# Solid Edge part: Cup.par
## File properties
Title: Cup
Author: DESYS
Template: Normal.par
Last saved by: Luca
Revision: 10
Application: Solid Edge
Tipo di contenuto documento: 0
Precisione: 0,990
Document Number: 8044
Revision: 0
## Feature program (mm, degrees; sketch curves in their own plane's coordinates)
lofted protrusion "unnamed LoftedProtrusion 1"
lofted cutout "unnamed LoftedCutout 1"
sketch for "unnamed Protrusion 1" plane through (0, 0, -90) normal (0, 0, -1) x-axis (1, 0, 0)
  circle centre (0, 0) radius 85
extrude "unnamed Protrusion 1" add finite 20 along +normal
sketch for "Foro_1" plane through (0, 0, -110) normal (0, 0, -1) x-axis (1, 0, 0)
  hole centre (0, 0) bore radius 25
hole "Foro_1" diameter 50 through
sketch for "Foro_2" plane through (0, 0, -110) normal (0, 0, -1) x-axis (0, 1, 0)
  hole centre (0, -70) bore radius 6
hole "Foro_2" diameter 12 finite
sketch for "unnamed Hole 1" plane through (0, 0, -110) normal (0, 0, -1) x-axis (0, 1, 0)
  hole centre (0, 70) bore radius 6
hole "unnamed Hole 1" finite
sketch for "Foro_4" plane through (0, 0, -110) normal (0, 0, -1) x-axis (0, 1, 0)
  hole centre (-70, 0) bore radius 6
hole "Foro_4" diameter 12 finite
sketch for "unnamed Hole 2" plane through (0, 0, -110) normal (0, 0, -1) x-axis (0, 1, 0)
  hole centre (70, 0) bore radius 6
hole "unnamed Hole 2" finite
sketch for "ExtrudedCutout_1" #1 plane through (0, 0, -110) normal (0, 0, -1) x-axis (0, 1, 0)
  circle centre (0, 0) radius 37.5
sketch for "ExtrudedCutout_1" #2 plane through (0, 0, -110) normal (0, 0, -1) x-axis (0, 1, 0)
  arc centre (-53.4571, -12.9358) radius 10 from (-61.3347, -6.7759) to (-63.1766, -15.2877) ccw
  arc centre (0, 0) radius 65 from (-15.2877, -63.1766) to (-63.1766, -15.2877) cw
  arc centre (-12.9358, -53.4571) radius 10 from (-15.2877, -63.1766) to (-6.7759, -61.3347) ccw
  arc centre (12.9358, -53.4571) radius 10 from (6.7759, -61.3347) to (15.2877, -63.1766) ccw
  arc centre (0, 0) radius 65 from (63.1766, -15.2877) to (15.2877, -63.1766) cw
  arc centre (53.4571, -12.9358) radius 10 from (63.1766, -15.2877) to (61.3347, -6.7759) ccw
  arc centre (53.4571, 12.9358) radius 10 from (61.3347, 6.7759) to (63.1766, 15.2877) ccw
  arc centre (12.9358, 53.4571) radius 10 from (15.2877, 63.1766) to (6.7759, 61.3347) ccw
  arc centre (-12.9358, 53.4571) radius 10 from (-6.7759, 61.3347) to (-15.2877, 63.1766) ccw
  arc centre (0, 0) radius 65 from (-63.1766, 15.2877) to (-15.2877, 63.1766) cw
  arc centre (-53.4571, 12.9358) radius 10 from (-63.1766, 15.2877) to (-61.3347, 6.7759) ccw
extrude "ExtrudedCutout_1" cut finite 15 along -normal
sketch for "Foro_6" plane through (0, 0, -110) normal (0, 0, -1) x-axis (0, 1, 0)
  hole centre (-70, 0) bore radius 11
hole "Foro_6" diameter 22 finite
sketch for "unnamed Hole 3" plane through (0, 0, -110) normal (0, 0, -1) x-axis (0, 1, 0)
  hole centre (70, 0) bore radius 11
hole "unnamed Hole 3" finite
pattern "unnamed Pattern 1" of "Foro_6", "unnamed Hole 3"
fillet "Rotondo_1" radius 10
fillet "Rotondo_2" radius 7
fillet "Rotondo_3" radius 7
fillet "Rotondo_5" radius 5
fillet "Rotondo_7" radius 7
fillet "Rotondo_8" radius 6
fillet "Rotondo_9" radius 10
pattern "unnamed Pattern 2" of "Foro_2", "unnamed Hole 1"
pattern "unnamed Pattern 3" of "Foro_4", "unnamed Hole 2"
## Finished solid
Body 1: solid body, 78 faces, 157 edges, 80 vertices.
  Faces by surface: torus 37, cylinder 25, plane 11, blend 4, spline 1
  Edges by curve: circle 127, line 16, intersection 14
Bounding box of the edges (mm; curved faces can reach further): 448.553 x 448.553 x 110.000, from (-224.2767, -224.2767, -110) to (224.2767, 224.2767, 0).
Cylindrical faces by radius (mm): R6 x4, R10 x8, R11 x6, R25 x1, R37.5 x1, R65 x4, R85 x1
Toroidal faces (ring radius, tube radius in mm): R3 r7 x8, R6 r5 x2, R15 r5 x8, R18 r7 x4, R32.5 r5 x1, R44.5 r7 x1, R58 r7 x4, R70 r5 x4, R73.9188 r180 x1, R80 r5 x2, R95 r10 x1, R219.2647 r6 x1
Planar faces by outward normal: +z 1, -z 10
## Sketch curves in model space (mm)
arc centre (-36.2383, 0, 144.7253) radius 230 from (-214.9968, 0, 0) through (-130.1638, 0, -65.2223) to (-25, 0, -85)
circle centre (0, 0, -85) radius 25
circle centre (0, 0, -85) radius 25
circle centre (0, 0, 0) radius 215
arc centre (-73.9188, 0, 89.6586) radius 180 from (-230, 0, 0) through (-168.8441, 0, -63.2766) to (-85, 0, -90)
circle centre (0, 0, -90) radius 85
circle centre (0, 0, 0) radius 230
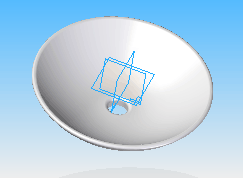
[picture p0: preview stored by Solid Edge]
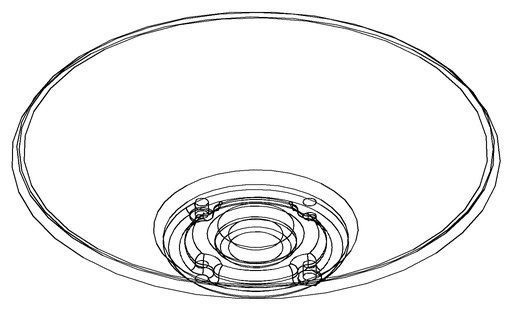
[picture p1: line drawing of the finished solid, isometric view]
